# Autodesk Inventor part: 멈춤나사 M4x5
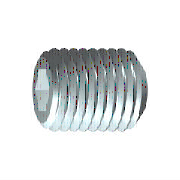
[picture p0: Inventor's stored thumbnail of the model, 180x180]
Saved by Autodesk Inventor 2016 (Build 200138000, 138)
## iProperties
IsCustomPart: 1
Created: 2012-02
Part Number: 멈춤나사 M4x5
Material: 강철, 연강
Description: 6각 소켓 머리 없는 멈춤 나사
Document SubType Name: Modeling
Standard: KS B 1028
Designer: mduedu
Standards Organization: KS
Language: ko-KR
Size Designation: 납작점M4x5
Categories: <MemberInstance><Categories><Category DisplayName="조임쇠" InternalName="e4da775c-781d-43d5-af7c-5136215cf5a6" Mnemonic="FSTN"><Category DisplayName="볼트" InternalN
Density: 7.85 g/cm^3
Appearance: 노란색
Mass: 0.401252 g
Surface Area: 0.994256 cm^2
Volume: 0.0511149 cm^3
Author: mduedu
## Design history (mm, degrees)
sketch "스케치1"
  geometry: L1 (0, 0)-(1.833, 0); L2 (5, 1.155)-(5, 2); L3 (5, 2)-(0, 2); L4 (5, 1.155)-(2.5, 1.155); L5 (2.5, 1.155)-(1.833, 0); L6 (0, -0.4)-(0, 2.4) reference; L7 (0, 2)-(0, 0)
  constraints: 13 end point, 3 parallel, 1 collinear, 1 perpendicular, 1 point on line
  dimensions: "d0" = 2.5 distance of L2.start L4.end (= INTI); "d1" = 60 deg angle of L5 L1; "d2" = 4 diameter of L3 L1 (= NND); "d3" = 2.3094 diameter of L4 L1 (= 1.1547 x SW); "d5" = 5 distance from line of L2 L3.end (= NLG)
revolve "본체" sketch "스케치1" stored, may be unused: angle "d6" = 90 deg
sketch "스케치2"
  geometry: L1 (-0.577, 1)-(0.577, 1); L2 (0.577, 1)-(1.155, 0); L3 (1.155, 0)-(0.577, -1); L4 (0.577, -1)-(-0.577, -1); L5 (-0.577, -1)-(-1.155, 0); L6 (-1.155, 0)-(-0.577, 1); A1 r 1.155 centre (0, 0) between (-0.577, 1) and (0.577, 1) reference; 2 further points
  constraints: 12 end point, 2 point on circle, 1 coincident, 1 horizontal, 11 other
extrude "슬롯" join sketch "스케치2" taper "d9" = 0 deg; stored distance "d21" = 10
workaxis "Work Axis1"
workplane "Work Plane1"
body "Solid1"
chamfer "모따기1" distance "d7" = 0.42941 (= -0.5 x GD1 + 0.5 x NND); stored, may be unused: angle "d8" = 45 deg (= FAWI), second distance "d29" = 0.42941 (= -0.5 x GD1 + 0.5 x NND)
feature "스레드" dims "d11" = 5 (= NLG), "d12" = 0
chamfer "모따기2" distance "d13" = 0.42941 (= -0.5 x GD1 + 0.5 x NND); stored, may be unused: angle "d14" = 45 deg (= FAWI), second distance "d30" = 0.42941 (= -0.5 x GD1 + 0.5 x NND)
other parameters: "NND" = 4 [user parameter; used in 5 equation terms], "NLG" = 5 [user parameter; used in 2 equation terms], "INTI" = 2.5 [user parameter; used in 1 equation term], "FAWI" = 45 deg [user parameter; used in 2 equation terms], "SW" = 2 [user parameter; used in 2 equation terms], "GD1" = 3.14117 (= THREADDIA - 1.2269 x PTC) [user parameter; used in 4 equation terms], "d4" = 0, "FAWI1" = 45 deg [user parameter], "d15" = 0, "d31" = 0, "GUL" = 0.42941 (= 0.61345 x PTC) [user parameter], "SPD" = 2.5 [user parameter], "TPU" = 14.28571 (computed from PTC) [user parameter], "TOA" = 30 deg [user parameter], "THREADDIA" = 4 [user parameter; used in 1 equation term], "PTC" = 0.7 [user parameter; used in 4 equation terms], "GAL" = 0.42941 (= 0.61345 x PTC) [user parameter], "E0" = 2.31 (= 1.155 x SW) [user parameter]
